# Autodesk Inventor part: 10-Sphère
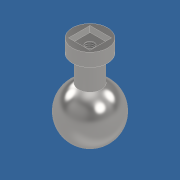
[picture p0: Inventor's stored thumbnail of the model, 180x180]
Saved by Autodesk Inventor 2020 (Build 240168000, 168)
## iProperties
Created: 2022-02
Part Number: 10-Sphère
Material: Acier, alliage
Document SubType Name: Modeling
Designer: Philippe
Density: 7.73 g/cm^3
Appearance: Semi-poli
Author: Philippe
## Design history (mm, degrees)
sketch "Esquisse1"
  geometry: L1 (0, 0)-(10, 0); L2 (10, 0)-(10, -7.5); L3 (10, -7.5)-(0, -7.5); L4 (0, -7.5)-(0, 0); L5 (0, -7.5)-(6.5, -7.5); L6 (6.5, -7.5)-(6.5, -22.149); L7 (6.5, -22.149)-(0, -22.149); L8 (0, -22.149)-(0, -7.5); L9 (0, -22.149)-(0, -51.3); A1 r 15.3 centre (0, -36) between (0, -51.3) and (6.5, -22.149); 1 further point
  constraints: 18 end point, 4 parallel, 2 horizontal, 2 perpendicular, 2 point on circle, 1 centre point, 1 point on line, 1 vertical
  dimensions: "d0" = 20 diameter of L2 L9; "d1" = 7.5 distance of L1.end L2.end; "d2" = 13 diameter of L6 L9; "d3" = 30.6 diameter of A1; "d4" = 36 distance from line of L1 A1.centre
revolve "Révolution1" sketch "Esquisse1" stored, may be unused: angle "d5" = 90 deg
sketch "Esquisse2"
  geometry: L1 (6.1, -6.1)-(-6.1, -6.1); L2 (-6.1, -6.1)-(-6.1, 6.1); L3 (-6.1, 6.1)-(6.1, 6.1); L4 (6.1, 6.1)-(6.1, -6.1); L5 (6.1, -6.1)-(-6.1, 6.1); L6 (-6.1, -6.1)-(6.1, 6.1); 1 further point
  constraints: 12 end point, 2 midpoint, 2 parallel, 2 perpendicular, 1 horizontal
  dimensions: "d6" = 12.2 distance of L1.end L2.end
extrude "Extrusion1" cut sketch "Esquisse2" distance "d7" = 3.4; taper "d8" = 0 deg
sketch "Esquisse3"
  geometry: 1 further point
hole "Perçage1" sketch "Esquisse3" at (0, 0) diameter "d9" = 4.917; stored, may be unused: countersink angle "d13" = 90 deg, drill point angle "d15" = 118 deg; dims "d10" = 18, "d11" = 4, "d12" = 2, "d14" = 23
node "Solide1"
